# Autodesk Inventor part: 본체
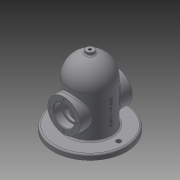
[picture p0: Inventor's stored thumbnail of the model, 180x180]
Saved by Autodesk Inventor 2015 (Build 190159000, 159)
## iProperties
Created: 2019-11
Part Number: 본체
Material: 일반
Document SubType Name: Modeling
Designer: Lineart
Density: 1 g/cm^3
Appearance: 기본값
Author: Lineart
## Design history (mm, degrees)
sketch "스케치1"
  geometry: C1 r 70 at (0, 0); 1 further point
  constraints: 1 centre point, 1 coincident
  dimensions: "d0" = 140 diameter of C1
extrude "돌출1" new body sketch "스케치1" distance "d1" = 10; taper "d2" = 0 deg
sketch "스케치2"
  geometry: C1 r 70 at (0, 0) reference; C2 r 40 at (0, 0); 1 further point
  constraints: 1 centre point, 1 coincident
  dimensions: "d3" = 80 diameter of C2
extrude "돌출2" join sketch "스케치2" distance "d4" = 80; taper "d5" = 0 deg
sketch "스케치3"
  geometry: L1 (40, 90)-(-40, 90) reference; L2 (-40, 10)-(40, 10) reference; L3 (70, 10)-(-70, 10) reference; L4 (-70, 0)-(70, 0) reference; L5 (0, 90)-(40, 90); L6 (40, 90)-(-40, 90) reference; L7 (0, 90)-(0, 130); A1 r 40 centre (0, 90) between (40, 90) and (0, 130); 1 further point
  constraints: 4 end point, 2 point on circle, 1 centre point, 1 collinear, 1 midpoint, 1 perpendicular
  dimensions: "d6" = 80 diameter of A1 (derived)
revolve "회전1" sketch "스케치3" stored, may be unused: angle "d7" = 90 deg
node "작업 평면1"
sketch "스케치4"
  geometry: C1 r 40 at (0, 0) reference; C2 r 40 at (0, 0) reference; C3 r 70 at (0, 0) reference; C4 r 7.5 at (0, 0); 1 further point
  constraints: 1 centre point, 1 coincident
  dimensions: "d9" = 15 diameter of C4
extrude "돌출3" join sketch "스케치4" distance "d10" = 50; taper "d11" = 0 deg
sketch "스케치5"
  geometry: L1 (-70, 0)-(70, 0) reference; C1 r 31 at (0, 50); 2 further points
  constraints: 1 centre point, 1 midpoint, 1 vertical alignment
  dimensions: "d12" = 62 diameter of C1; "d13" = 50 distance from line of L1 C1.centre
extrude "돌출4" join sketch "스케치5" stored distance "d14" = 100; taper "d15" = 0 deg
sketch "스케치6"
  geometry: C1 r 40 at (0, 0) reference; C2 r 70 at (0, 0) reference; C3 r 30 at (0, 0); 1 further point
  constraints: 1 centre point, 1 coincident
  dimensions: "d16" = 60 diameter of C3
extrude "돌출5" cut sketch "스케치6" distance "d17" = 90; taper "d18" = 0 deg
sketch "스케치7"
  geometry: L1 (30, 90)-(-30, 90) reference; L2 (30, 0)-(-30, 0) reference; L3 (0, 120)-(0, 90); L4 (0, 90)-(30, 90); L5 (40, 90)-(-40, 90) reference; A1 r 30 centre (0, 90) between (30, 90) and (0, 120); 1 further point
  constraints: 4 end point, 2 point on circle, 1 centre point, 1 collinear, 1 midpoint, 1 vertical
  dimensions: "d19" = 60 diameter of A1 (derived)
revolve "회전2" sketch "스케치7" stored, may be unused: angle "d20" = 90 deg
sketch "스케치8"
  geometry: C1 r 31 at (0, 0) reference; C2 r 20 at (0, 0); 1 further point
  constraints: 1 centre point, 1 coincident
  dimensions: "d21" = 40 diameter of C2
extrude "돌출6" cut sketch "스케치8" distance "d22" = 15; taper "d23" = 0 deg
sketch "스케치9"
  geometry: C1 r 20 at (0, 0) reference; C2 r 20 at (0, 0) reference; C3 r 16.5 at (0, 0); 1 further point
  constraints: 1 centre point, 1 coincident
  dimensions: "d24" = 33 diameter of C3
extrude "돌출7" cut sketch "스케치9" distance "d25" = 30; taper "d26" = 0 deg
sketch "스케치10"
  geometry: C1 r 20 at (0, 0) reference; C2 r 31 at (0, 0) reference; 2 further points
  constraints: 1 vertical alignment
  dimensions: "d27" = 26 distance of C1.centre point (0, 26)
hole "구멍1" sketch "스케치10" at (0, 26) diameter "d28" = 3.242; stored, may be unused: countersink angle "d32" = 90 deg, drill point angle "d34" = 118 deg; dims "d29" = 8, "d30" = 4, "d31" = 2, "d33" = 10
sketch "스케치11"
  geometry: C1 r 7.5 at (0, 0) reference; 2 further points
  constraints: 1 coincident
hole "구멍2" sketch "스케치11" at (0, 0) diameter "d38" = 5.188; stored, may be unused: countersink angle "d42" = 90 deg, drill point angle "d44" = 0 deg; dims "d39" = 12, "d40" = 4, "d41" = 2, "d43" = 30
sketch "스케치12"
  geometry: C1 r 40 at (0, 0) reference; C2 r 70 at (0, 0) reference; 3 further points
  constraints: 2 horizontal alignment
  dimensions: "d54" = 55 distance of point (0, 0) point (-55, 0); "d55" = 55 distance of point (55, 0) point (0, 0)
hole "구멍3" sketch "스케치12" at (55, 0), (-55, 0) diameter "d47" = 9; stored, may be unused: countersink angle "d51" = 90 deg, drill point angle "d53" = 0 deg; dims "d48" = 12, "d49" = 4, "d50" = 2, "d52" = 30
fillet "모깎기1" dims "d56" = 3
fillet "모깎기2" dims "d57" = 0.3
chamfer "모따기1" distance "d58" = 1; stored, may be unused: second distance "d59" = 2, angle "d60" = 45 deg
node "작업 평면2"
sketch "스케치14"
  geometry: L1 (-10, 70)-(-10, -70) reference; 3 further points
  constraints: 1 horizontal alignment, 1 midpoint, 1 other
  dimensions: "d61" = 50 distance from line of L1 point (40, 0)
feature "엠보싱1" sketch "스케치14" dims "d1" = 10, "d2" = 0, "d7" = 90 deg, "d62" = 0.5, "d63" = 0
node "솔리드1"
mirror "대칭1"
pattern_circular "원형 패턴1" dims angle "d36" = 360 deg
mirror "대칭2"
node "투영된 루프1"
node "투영된 루프2"
node "투영된 루프3"
node "투영된 루프4"
node "투영된 루프5"
node "투영된 루프6"
node "투영된 루프7"
node "투영된 루프8"
node "투영된 루프9"
node "투영된 루프10"
node "투영된 루프11"
node "투영된 루프12"
other parameters: "d8" = -135
